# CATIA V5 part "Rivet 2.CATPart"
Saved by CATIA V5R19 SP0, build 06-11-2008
Part number: Rivet 2
Bounding box of the stored display mesh (mm): x -7.388 to 7.388, y -1.546 to 16.546, z -7.49 to 7.49
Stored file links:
  G:\EU_thinkMotion\CFAO_2010\St2M_groupe2\St2M_groupe2\csayed\csayed\csayed\Rivet 2.CATPart
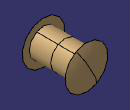
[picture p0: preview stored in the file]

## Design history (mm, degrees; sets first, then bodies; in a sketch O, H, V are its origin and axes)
Body1 (main body)
  Sketch1 on yz-plane, origin (0, 0, 0), H (0, 1, 0), V (0, 0, 1)
    line L1 (0, 5) -> (0, 7.5)
    point P1 (0, 7.5)
    arc A1 centre (9.3268, 1.6682) radius 11 from (0, 7.5) to (-1.5459, 0) ccw
    point P2 (9.3268, 1.6682)
    line L2 (0, 5) -> (7.5, 5)
    point P3 (0, 5)
    point P4 (7.5, 5)
    construction line L3 (7.5, 11.3892) -> (7.5, -7.1354)
    point P7 (15, 7.5)
    arc A2 centre (5.6732, 1.6682) radius 11 from (15, 7.5) to (16.5459, 0) cw
    line L4 (15, 5) -> (15, 7.5)
    point P9 (7.5, 5)
    point P10 (15, 5)
    line L5 (15, 5) -> (7.5, 5)
    line L6 (-1.5459, 0) -> (16.5459, 0)
    point P11 (-1.5459, 0)
    distance P2 A1 = 11
    distance L6 L2 = 5
    vertical: L1 V, L3 V
    horizontal: L2 H, L6 H
    symmetry: P1 P7 L3, A1 A2 L3, L1 L4 L3, P4 P9 L3, P3 P10 L3, L2 L5 L3
    coincidence: P11 H, P4 P9
  Shaft1: profile Sketch1, axis Sketch1.L6, angle 360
